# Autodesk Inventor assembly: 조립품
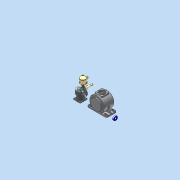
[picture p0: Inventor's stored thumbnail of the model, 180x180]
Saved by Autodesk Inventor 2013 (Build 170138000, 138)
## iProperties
Created: 2415-06
Part Number: 조립품
Document SubType Name: Assembly
Designer: Administrator
Author: Administrator
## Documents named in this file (15)
- C:\Users\Administrator\Desktop\450606V1003\조립품.iam
- C:\Users\Administrator\Desktop\450606V1003\본체.ipt
- C:\Users\Administrator\Desktop\450606V1003\M4x0.7.ipt
- C:\Users\Administrator\Desktop\450606V1003\M5x0.8.ipt
- C:\Users\Administrator\Desktop\450606V1003\메인 크랭크 축-구동부.ipt
- C:\Users\Administrator\Desktop\450606V1003\메인커버.ipt
- C:\Users\Administrator\Desktop\450606V1003\베어링 6204.ipt
- C:\Users\Administrator\Desktop\450606V1003\베어링 NA 4902.ipt
- C:\Users\Administrator\Desktop\450606V1003\실린더.ipt
- C:\Users\Administrator\Desktop\450606V1003\실린더헤드.ipt
- C:\Users\Administrator\Desktop\450606V1003\오일실.ipt
- C:\Users\Administrator\Desktop\450606V1003\커넥팅 로드.ipt
- C:\Users\Administrator\Desktop\450606V1003\크랭크 서브축.ipt
- C:\Users\Administrator\Desktop\450606V1003\피스톤 핀.ipt
- C:\Users\Administrator\Desktop\450606V1003\피스톤.ipt
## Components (7 placed, 4 different names)
1. M5x0.8:1
2. 피스톤 핀:1
3. 피스톤:1
4. M4x0.7:1 — 각도:1
5. M4x0.7:2
6. M4x0.7:3
7. M4x0.7:4
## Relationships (1: Angle 1)
- 각도:1 [Angle]: M4x0.7:1
